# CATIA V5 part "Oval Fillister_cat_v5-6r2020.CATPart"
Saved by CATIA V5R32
Part number: Oval Fillister
Bounding box of the stored display mesh (mm): x -6 to 6, y -5.85 to 5.85, z -8 to 3.6
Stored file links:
  D:\PROJECTS\Project 2022\CATIA V5 6R 2022\Resources\Tutorial Files\c13_catia_v5_6r2022_tut\c13tut2\Bench vice\Oval Fillister_cat_v5-6r2020.CATPart
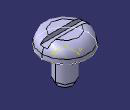
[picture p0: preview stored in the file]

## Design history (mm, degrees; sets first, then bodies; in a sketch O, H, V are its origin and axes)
Body1 (main body)
  Sketch1 on xy-plane, origin (0, 0, 0), H (1, 0, 0), V (0, 1, 0)
    circle A1 centre (0, 0) radius 6
    radius A1 = 6
  Pad1: profile Sketch1, direction (0, 0, 1), length 3.6
  Sketch2 on face of Pad1, origin (0, 0, 0), H (1, 0, 0), V (0, -1, 0)
    circle A1 centre (0, 0) radius 2.5
    radius A1 = 2.5
  Pad2: profile Sketch2, direction (0, 0, -1), length 7
  Sketch3 on face of Pad2, origin (0, 0, -7), H (1, 0, 0), V (0, -1, 0)
    circle A1 centre (0, 0) radius 2
    radius A1 = 2
  Pad3: profile Sketch3, direction (0, 0, -1), length 1
  Fillet1: radius 2.5, on 1 edge
  Sketch4 on yz-plane, origin (0, 0, 0), H (0, 1, 0), V (0, 0, 1)
    line L1 (-0.95, 4.5549) -> (0.95, 4.5549)
    line L2 (0.95, 4.5549) -> (0.95, 2.5)
    line L3 (0.95, 2.5) -> (-0.95, 2.5)
    line L4 (-0.95, 2.5) -> (-0.95, 4.5549)
    distance H L3 = 2.5
    distance L2 V = 0.95
    length L1 = 1.9
    horizontal: L1 H, L3 H
    vertical: L2 V, L4 V
  Pocket1: profile Sketch4, direction (-1, 0, 0), length 8, mirrored extent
